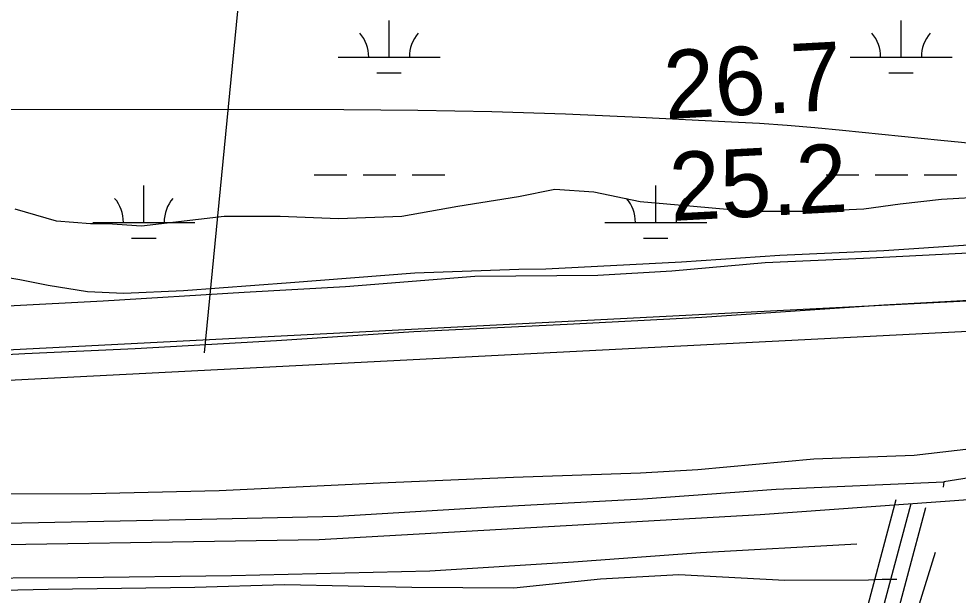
# Model space of a CAD drawing. Extents: x 3297772 to 3335630, y 634068 to 659439.
# Drawn here: x 3325853 to 3326774, y 644667 to 645232 of the extents above; entities that cross this region are included whole.
import ezdxf

# ---------------------------------------------------------------- set-up
doc = ezdxf.new("R2010")
doc.units = 0
for name, color, linetype in [('V-DTCH-CNTR', 7, 'Continuous'), ('V-FLOD-BASE', 7, 'Continuous'), ('V-LEVE-TOET', 7, 'Continuous'), ('V-RIVR-RANG', 7, 'Continuous'), ('V-ROAD-CNTR', 7, 'Continuous'), ('V-SITE-VEGE', 7, 'Continuous'), ('V-SURV-LINE', 7, 'Continuous'), ('V-TOPO-MAJR', 7, 'Continuous'), ('V-TOPO-SHOR', 7, 'Continuous'), ('V-WETL-SWMP', 7, 'Continuous')]:
    doc.layers.add(name, color=color, linetype=linetype)

msp = doc.modelspace()

# ---------------------------------------------------------------- linework, layer by layer
at = {"layer": 'V-DTCH-CNTR'}
msp.add_lwpolyline([(3326713.32, 644682.69), (3326698.93, 644682.71), (3326685.71, 644681.94), (3326603.64, 644681.65), (3326499.8, 644687.22), (3326422.79, 644683.03), (3326338, 644674.18), (3326238.04, 644674.69), (3326113.2, 644677.55), (3326025.3, 644674.93), (3325881.4, 644672.77), (3325777.03, 644670.59)], dxfattribs=at)
at = {"layer": 'V-FLOD-BASE'}
msp.add_lwpolyline([(3325761.93, 644898.77), (3325858.67, 644904.08), (3325966.63, 644908.98), (3326105.16, 644916.95), (3326239.82, 644925.69), (3326390.34, 644932.86), (3326522.29, 644939.68), (3326700.68, 644951.85), (3326819.86, 644958.29), (3326951.81, 644962.01), (3327092.27, 644967.65), (3327253.63, 644975.2), (3327410.34, 644981.98), (3327574.79, 644988.37), (3327744.28, 644998.62), (3327894.42, 645006.96)], dxfattribs=at)
at = {"layer": 'V-LEVE-TOET'}
for points in [[(3325841.82, 644950.68), (3325935.28, 644955.66), (3326073.71, 644964.1), (3326173.04, 644969.85), (3326299.74, 644979.87), (3326420.18, 644980.9), (3326492.91, 644985.12), (3326584.42, 644993.22), (3326680.62, 644997.41), (3326777.2, 645002.38), (3326869.1, 645005.4), (3326966.07, 645005.29), (3327012.6, 645007.19), (3327099.81, 645012.17), (3327193.66, 645017.15), (3327303.54, 645024.84), (3327376.67, 645026.71), (3327443.93, 645030.15), (3327534.65, 645032.39), (3327624.98, 645036.59), (3327750.9, 645047.78), (3327843.18, 645050.02)], [(3326874.18, 644820.53), (3326814.73, 644813.95), (3326730.26, 644804.27), (3326632.11, 644800.48), (3326518.31, 644790.05), (3326462, 644786.99), (3326337.65, 644782.44), (3326207.04, 644777.12), (3326049.06, 644769.48), (3325923.93, 644766.5), (3325803.16, 644766.34)]]:
    msp.add_lwpolyline(points, dxfattribs=at)
at = {"layer": 'V-RIVR-RANG'}
msp.add_line((3326034.55, 644904.78), (3326147.58, 646059.27), dxfattribs=at)
at = {"layer": 'V-ROAD-CNTR'}
for points in [[(3325736.13, 644715.28), (3326147.09, 644721.96), (3326579.39, 644746.24), (3326860.44, 644766.74), (3327040, 644782.69), (3327404.99, 644790.94), (3327728.58, 644805.03), (3328364.95, 644841.2), (3328961.02, 644870.02), (3329423.14, 644897.99), (3329955.72, 644924.78), (3330565.28, 644957.4), (3330772.61, 644967.85), (3331179.88, 644989.49), (3331440.97, 645002.91)], [(3326177.61, 643088.46), (3326266.97, 643362.72), (3326489.71, 644051.52), (3326677.15, 644627.21), (3326712.86, 644760.9)], [(3325033.86, 639493.96), (3325141.48, 639838.56), (3325256.71, 640197.97), (3325394.36, 640626.86), (3325549.87, 641104.97), (3325705.82, 641583.86), (3325774.67, 641801.83), (3325996.62, 642476.76), (3326177.23, 643038.9), (3326281.24, 643358.09), (3326503.98, 644046.89), (3326691.54, 644622.95), (3326727.35, 644757.03)], [(3326247.15, 643205.06), (3326295.51, 643353.46), (3326518.25, 644042.26), (3326705.92, 644618.69), (3326741.85, 644753.16)]]:
    msp.add_lwpolyline(points, dxfattribs=at)
at = {"layer": 'V-SITE-VEGE'}
for points in [[(3326802.6, 645057.56), (3326757.31, 645055.17), (3326716.78, 645050.41), (3326681.02, 645045.63), (3326630.96, 645043.25), (3326568.98, 645043.25), (3326514.14, 645048.02), (3326461.7, 645052.79), (3326416.4, 645062.33), (3326378.26, 645064.71), (3326342.5, 645057.56)], [(3326342.5, 645057.56), (3326282.9, 645048.02), (3326228.07, 645038.48), (3326166.08, 645036.09), (3326108.87, 645038.48), (3326054.04, 645038.48), (3325972.98, 645028.94), (3325939.61, 645031.32), (3325922.92, 645031.32), (3325889.54, 645033.71), (3325849.02, 645045.63)]]:
    msp.add_lwpolyline(points, dxfattribs=at)
at = {"layer": 'V-SURV-LINE'}
for points in [[(3325834.7, 644907.3), (3328221, 645029.14)], [(3328222.51, 644999.17), (3325836.21, 644877.34)]]:
    msp.add_lwpolyline(points, dxfattribs=at)
at = {"layer": 'V-TOPO-MAJR'}
msp.add_lwpolyline([(3326878.57, 645100.29), (3326837.92, 645104.47), (3326817.6, 645106.56), (3326797.27, 645108.65), (3326776.94, 645110.73), (3326756.62, 645112.8), (3326660.21, 645122.64), (3326633.05, 645125.2), (3326605.88, 645127.47), (3326578.67, 645129.33), (3326551.44, 645130.9), (3326461.13, 645135.42), (3326388.71, 645138.51), (3326316.28, 645140.89), (3326243.82, 645142.22), (3326171.34, 645142.83), (3325818.04, 645143.23)], dxfattribs=at)
at = {"layer": 'V-TOPO-SHOR'}
msp.add_line((3326759.33, 644778.2), (3326758.73, 644773.17), dxfattribs=at)
for points in [[(3326888.86, 644789.33), (3326802.9, 644785.15), (3326759.33, 644778.2)], [(3325774.16, 644736.56), (3325871.78, 644738.39), (3326032.01, 644741.7), (3326165.42, 644744.66), (3326312.05, 644753.44), (3326464.52, 644761.82), (3326595.2, 644771), (3326759.33, 644778.2)], [(3325783.04, 644684.05), (3325910.61, 644684.68), (3326061.12, 644686.45), (3326255.58, 644691.28), (3326396.38, 644700.06), (3326520.85, 644709.25), (3326674.09, 644717.62)], [(3326751.09, 644708.98), (3326733.52, 644653.39), (3326694.48, 644531.31), (3326653.9, 644407.68), (3326616.42, 644290.27), (3326563.72, 644123.49), (3326504.39, 643936.49)]]:
    msp.add_lwpolyline(points, dxfattribs=at)
at = {"layer": 'V-WETL-SWMP'}
for p, q in [((3326215.62, 645194.48), (3326215.62, 645230.48)), ((3326717.53, 645194.48), (3326717.53, 645230.48)), ((3326165.62, 645194.48), (3326265.62, 645194.48)), ((3326667.53, 645194.48), (3326767.53, 645194.48)), ((3326203.62, 645179.05), (3326227.62, 645179.05)), ((3326705.53, 645179.05), (3326729.53, 645179.05)), ((3326142.21, 645079.05), (3326174.21, 645079.05)), ((3326190.21, 645079.05), (3326222.21, 645079.05)), ((3326238.21, 645079.05), (3326270.21, 645079.05)), ((3326644.12, 645079.05), (3326676.12, 645079.05)), ((3326692.12, 645079.05), (3326724.12, 645079.05)), ((3326740.12, 645079.05), (3326772.12, 645079.05)), ((3325975.15, 645032.62), (3325975.15, 645068.62)), ((3326477.06, 645032.62), (3326477.06, 645068.62)), ((3325925.15, 645032.62), (3326025.15, 645032.62)), ((3326427.06, 645032.62), (3326527.06, 645032.62)), ((3325963.15, 645017.19), (3325987.15, 645017.19)), ((3326465.06, 645017.19), (3326489.06, 645017.19))]:
    msp.add_line(p, q, dxfattribs=at)
msp.add_lwpolyline([(3326783.5, 645010.31), (3326700.52, 645004.56), (3326598.85, 645000.01), (3326502.23, 644993.5), (3326369.39, 644986.64), (3326342.9, 644986.28), (3326240.84, 644982.89), (3326118.9, 644973.3), (3326014.1, 644965.63), (3325955.67, 644962.97), (3325919.83, 644964.57), (3325881.28, 644970.84), (3325853.62, 644976.33), (3325824.03, 644981.04)], dxfattribs=at)
for centre, start, end in [((3326160.38, 645194.96), 359.22818, 40.77184), ((3326270.86, 645194.96), 139.22817, 180.77183), ((3326662.28, 645194.96), 359.22818, 40.77184), ((3326772.77, 645194.96), 139.22817, 180.77183), ((3325919.9, 645033.1), 359.22818, 40.77184), ((3326030.39, 645033.1), 139.22817, 180.77183), ((3326421.81, 645033.1), 359.22818, 40.77184), ((3326532.3, 645033.1), 139.22817, 180.77183)]:
    msp.add_arc(centre, 35.25, start, end, dxfattribs=at)

# ---------------------------------------------------------------- texts
at = {"layer": 'V-RIVR-RANG'}
for s, p in [('26.7', (3326486.65, 645133.76)), ('25.2', (3326492.24, 645033.92))]:
    msp.add_text(s, height=67, rotation=3.05833, dxfattribs=at).set_placement(p)

doc.saveas('drawing.dxf')
